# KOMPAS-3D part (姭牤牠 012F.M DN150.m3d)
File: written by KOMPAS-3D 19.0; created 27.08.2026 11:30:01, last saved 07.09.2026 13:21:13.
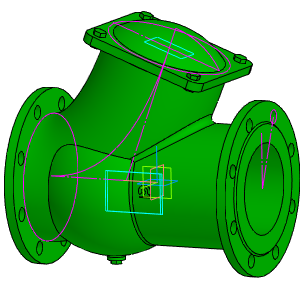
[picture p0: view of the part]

Document properties: Автор: Энергия; Полное имя файла: Z:\3.Личные\kachalov\001_3d для проектировщиков\х.х Тип 012F\012F.M\Клапан 012F.M DN150.m3d

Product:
- Part/product: (unnamed)  | designation Клапан 012F.M DN150
    Масса: 108.042

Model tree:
1. Эскиз:1
2. Элемент вращения:1
     Угол 1 = 360
3. Эскиз:2  (with: Элемент вращения:1)
4. Перпендикулярная плоскость:1
5. Эскиз:3
6. Эскиз:12  (with: Элемент вращения:1)
7. Элемент по сечениям:1
8. Эскиз:7
9. Элемент выдавливания:2
     Расстояние 2 = 15
10. Эскиз:9  (with: Элемент выдавливания:2)
11. Элемент вращения:2
     Угол 1 = 360
12. Эскиз:10  (with: Элемент вращения:1)
13. Элемент выдавливания:3  (with: Элемент вращения:1)
     Расстояние 2 = 16
14. Массив по концентрической сетке:1  (with: Элемент выдавливания:3, Эскиз:10, Элемент вращения:1)  (8 pattern instances)
     Шаг 2 = 360
15. Эскиз:11  (with: Элемент вращения:1)
16. Элемент выдавливания:4  (with: Элемент вращения:1)
     Расстояние 2 = 16
17. Массив по концентрической сетке:2  (with: Элемент выдавливания:4, Эскиз:11, Элемент вращения:1)  (8 pattern instances)
     Шаг 2 = 360
18. Скругление:6  (with: Элемент выдавливания:2)
     Радиус = 3
19. Эскиз:13  (with: Элемент выдавливания:2)
20. Элемент выдавливания:5  (with: Элемент выдавливания:2)
     Расстояние 1 = 7; Расстояние 2 = 20.5; Смещение 2 = 5.5
21. Массив по концентрической сетке:3  (with: Элемент выдавливания:5, Эскиз:9, Эскиз:13, Элемент вращения:2)  (4 pattern instances)
     Шаг 2 = 360
22. Касательная плоскость:1  (with: Элемент вращения:1)
     Угол = 90
23. Смещенная плоскость:1
     Расстояние = 1
24. Эскиз:14
25. Элемент выдавливания:6  (with: Элемент вращения:1)
     Расстояние 1 = -1.0002; Расстояние 2 = 1
26. Эскиз:15  (with: Элемент вращения:1)
27. Элемент вращения:3  (with: Элемент вращения:1)
     Угол 1 = 360
28. Скругление:10  (with: Элемент вращения:3, Элемент по сечениям:1)
     Радиус = 10
29. Эскиз:16
30. Элемент выдавливания:7
     Расстояние 1 = 130
31. Эскиз:17  (with: Элемент выдавливания:7)
32. Элемент выдавливания:8
     Расстояние 1 = 6.5
33. Эскиз:18  (with: Элемент вращения:1)
34. Элемент выдавливания:9
     Расстояние 2 = 400
35. Скругление:11  (with: Элемент выдавливания:2)
     Радиус = 20
36. Скругление:12  (with: Элемент выдавливания:7)
     Радиус = 3
37. Эскиз:19  (with: Скругление:11, Элемент выдавливания:5)
38. Эскиз:20  (with: Скругление:11)

Expressions: Dn/2; D/2; D2/2; D2/2-5; 360/(2*n); 360/(n*2); D2-6; D2-5; 220/2
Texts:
  Клапан 012F.M DN150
